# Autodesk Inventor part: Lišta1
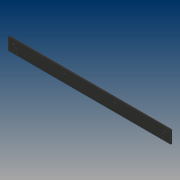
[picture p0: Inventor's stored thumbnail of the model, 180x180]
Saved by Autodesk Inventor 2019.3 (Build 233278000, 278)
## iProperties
Created: 2019-02
Part Number: Lišta1
Material: PVC, nepoplastované
Document SubType Name: Modeling
Designer: B-hon
Density: 1.29 g/cm^3
Appearance: Guma – černá
Author: B-hon
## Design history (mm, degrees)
sketch "Náčrt1"
  geometry: L1 (352, -27)-(-352, -27); L2 (-352, -27)-(-352, 27); L3 (-352, 27)-(352, 27); L4 (352, 27)-(352, -27); L5 (352, -27)-(-352, 27); L6 (-352, -27)-(352, 27); 1 further point
  constraints: 12 end point, 2 midpoint, 2 parallel, 1 horizontal, 1 perpendicular
  dimensions: "d0" = 704 distance of L2.end L3.end; "d1" = 54 distance of L1.end L2.end
extrude "Vysunutí1" new body sketch "Náčrt1" distance "d2" = 5; taper "d3" = 0 deg
sketch "Náčrt2"
  geometry: L1 (-352, 27)-(-352, -27) reference; L2 (352, 27)-(-352, 27) reference; 2 further points
  dimensions: "d4" = 22 distance from line of L1 point (-330, 10.75); "d5" = 16.25 distance from line of point (-330, 10.75) L2
hole "Díra1" sketch "Náčrt2" at (-330, 10.75) diameter "d6" = 5.5; stored, may be unused: countersink angle "d10" = 90 deg, drill point angle "d12" = 0 deg; dims "d7" = 6, "d8" = 9.5, "d9" = 2, "d11" = 8
pattern_linear "Obdélníkové pole1" dims "d15" = 220
sketch "Náčrt3"
  geometry: L1 (-352, -27)-(352, -27) reference; L2 (-352, 27)-(-352, -27) reference; L3 (352, -27)-(352, 27) reference; 5 further points
  constraints: 2 horizontal alignment, 2 vertical alignment
  dimensions: "d16" = 7 distance from line of L1 point (-316, -20); "d17" = 36 distance from line of L2 point (-316, -2); "d18" = 36 distance from line of L3 point (316, -20); "d19" = 18 distance of point (-316, -2) point (-316, -20)
hole "Díra2" sketch "Náčrt3" at (-316, -20), (-316, -2), (316, -20), (316, -2) diameter "d20" = 5.5; stored, may be unused: countersink angle "d24" = 90 deg, drill point angle "d26" = 0 deg; dims "d21" = 6, "d22" = 9.5, "d23" = 2, "d25" = 8
node "Těleso1"
